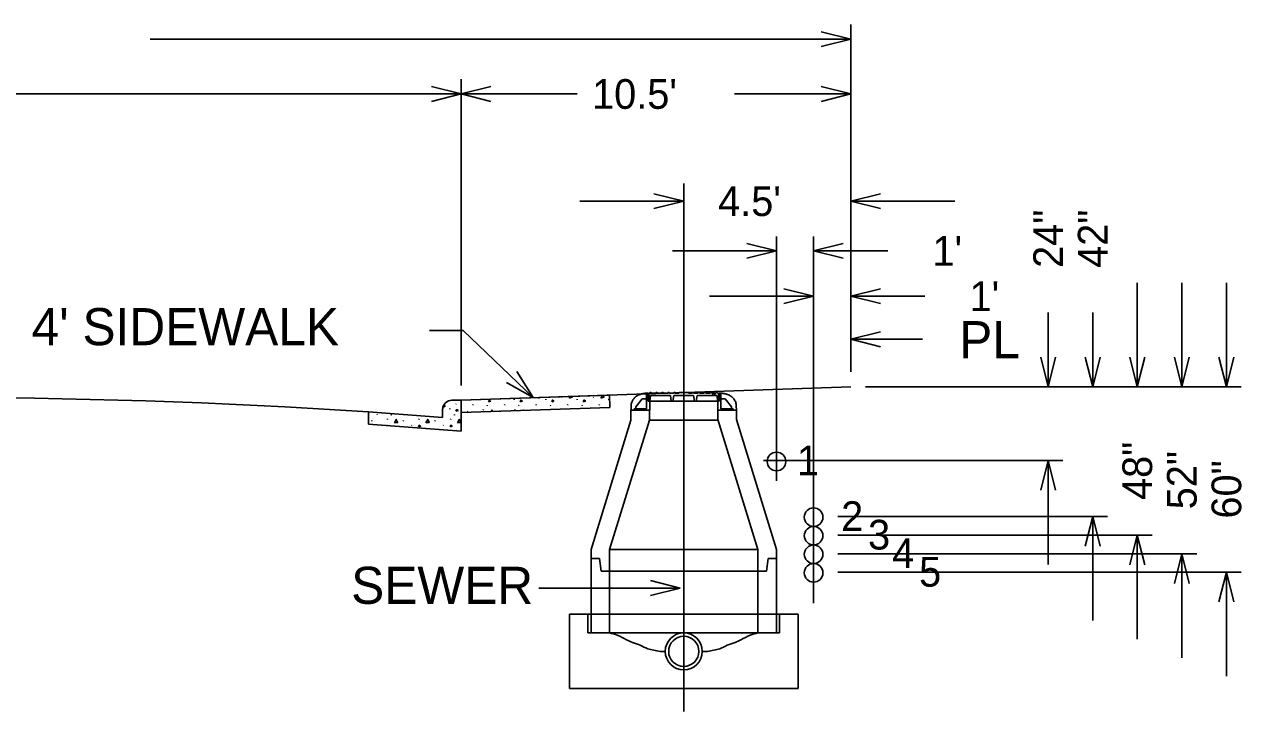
# Model space of a CAD drawing. Extents: x 524397 to 525117, y 3701341 to 3701821.
# Drawn here: x 524790.7 to 524856.3, y 3701669.5 to 3701706.5 of the extents above; entities that cross this region are included whole.
import ezdxf

# ---------------------------------------------------------------- set-up
doc = ezdxf.new("R2010")
doc.units = 0
doc.layers.add('Level 11', color=7, linetype='Continuous')

msp = doc.modelspace()

# ---------------------------------------------------------------- linework, layer by layer
at = {"layer": 'Level 11'}
for p, q in [((524835.239, 3701687.802), (524835.239, 3701706.53)), ((524797.484, 3701705.729), (524835.239, 3701705.729)), ((524833.638, 3701706.13), (524835.239, 3701705.729)), ((524835.239, 3701705.729), (524833.638, 3701705.329)), ((524812.642, 3701703.179), (524814.243, 3701702.779)), ((524814.243, 3701687.069), (524814.243, 3701703.579)), ((524814.243, 3701702.779), (524815.844, 3701703.179)), ((524833.638, 3701703.179), (524835.239, 3701702.779)), ((524835.239, 3701687.802), (524835.239, 3701703.579)), ((524787.897, 3701702.779), (524814.243, 3701702.779)), ((524814.243, 3701702.779), (524812.642, 3701702.379)), ((524820.499, 3701702.779), (524814.243, 3701702.779)), ((524815.844, 3701702.379), (524814.243, 3701702.779)), ((524828.983, 3701702.779), (524835.239, 3701702.779)), ((524835.239, 3701702.779), (524833.638, 3701702.379)), ((524835.239, 3701687.802), (524835.239, 3701700.542)), ((524826.239, 3701669.489), (524826.239, 3701697.958)), ((524824.638, 3701697.402), (524826.239, 3701697.002)), ((524835.239, 3701697.002), (524836.84, 3701697.402)), ((524820.635, 3701697.002), (524826.239, 3701697.002)), ((524826.239, 3701697.002), (524824.638, 3701696.601)), ((524840.842, 3701697.002), (524835.239, 3701697.002)), ((524836.84, 3701696.601), (524835.239, 3701697.002)), ((524829.638, 3701694.722), (524831.239, 3701694.321)), ((524831.239, 3701681.923), (524831.239, 3701695.099)), ((524833.239, 3701675.335), (524833.239, 3701695.099)), ((524833.239, 3701694.321), (524834.84, 3701694.722)), ((524825.635, 3701694.321), (524831.239, 3701694.321)), ((524831.239, 3701694.321), (524829.638, 3701693.921)), ((524837.241, 3701694.321), (524833.239, 3701694.321)), ((524834.84, 3701693.921), (524833.239, 3701694.321)), ((524850.681, 3701692.605), (524850.681, 3701687.001)), ((524853.083, 3701692.605), (524853.083, 3701687.001)), ((524855.484, 3701692.605), (524855.484, 3701687.001)), ((524827.635, 3701691.88), (524833.239, 3701691.88)), ((524831.638, 3701692.28), (524833.239, 3701691.88)), ((524833.239, 3701691.88), (524831.638, 3701691.479)), ((524835.239, 3701691.88), (524836.84, 3701692.28)), ((524839.241, 3701691.88), (524835.239, 3701691.88)), ((524836.84, 3701691.479), (524835.239, 3701691.88)), ((524845.878, 3701691.004), (524845.878, 3701687.001)), ((524848.28, 3701691.004), (524848.28, 3701687.001)), ((524814.352, 3701690.028), (524812.547, 3701690.028)), ((524818.13, 3701686.417), (524814.352, 3701690.028)), ((524835.239, 3701689.555), (524836.84, 3701689.955)), ((524835.239, 3701689.555), (524839.115, 3701689.555)), ((524836.84, 3701689.154), (524835.239, 3701689.555)), ((524845.878, 3701687.001), (524845.478, 3701688.602)), ((524846.279, 3701688.602), (524845.878, 3701687.001)), ((524848.28, 3701687.001), (524847.88, 3701688.602)), ((524848.68, 3701688.602), (524848.28, 3701687.001)), ((524850.681, 3701687.001), (524850.281, 3701688.602)), ((524851.081, 3701688.602), (524850.681, 3701687.001)), ((524853.083, 3701687.001), (524852.682, 3701688.602)), ((524853.483, 3701688.602), (524853.083, 3701687.001)), ((524855.484, 3701687.001), (524855.084, 3701688.602)), ((524855.884, 3701688.602), (524855.484, 3701687.001)), ((524818.13, 3701686.417), (524816.696, 3701687.234)), ((524817.249, 3701687.812), (524818.13, 3701686.417)), ((524835.239, 3701687.001), (524814.249, 3701686.269)), ((524824.24, 3701686.646), (524824.24, 3701686.646)), ((524824.24, 3701686.646), (524824.324, 3701686.646)), ((524824.24, 3701686.354), (524824.24, 3701686.646)), ((524824.323, 3701686.229), (524824.324, 3701686.646)), ((524824.365, 3701686.646), (524824.365, 3701686.229)), ((524824.407, 3701686.646), (524824.365, 3701686.646)), ((524824.365, 3701686.646), (524824.407, 3701686.646)), ((524824.365, 3701686.229), (524824.365, 3701686.646)), ((524824.407, 3701686.646), (524824.423, 3701686.687)), ((524824.407, 3701686.646), (524824.423, 3701686.687)), ((524824.423, 3701686.687), (524824.485, 3701686.687)), ((524824.423, 3701686.687), (524824.485, 3701686.687)), ((524824.5, 3701686.646), (524824.485, 3701686.687)), ((524824.485, 3701686.687), (524824.5, 3701686.646)), ((524824.731, 3701686.646), (524824.5, 3701686.646)), ((524824.5, 3701686.646), (524824.731, 3701686.646)), ((524824.731, 3701686.646), (524824.746, 3701686.687)), ((524824.731, 3701686.646), (524824.746, 3701686.687)), ((524824.746, 3701686.687), (524824.806, 3701686.687)), ((524824.746, 3701686.687), (524824.806, 3701686.687)), ((524824.821, 3701686.646), (524824.806, 3701686.687)), ((524824.806, 3701686.687), (524824.821, 3701686.646)), ((524825.047, 3701686.646), (524824.821, 3701686.646)), ((524824.821, 3701686.646), (524825.047, 3701686.646)), ((524825.047, 3701686.646), (524825.062, 3701686.687)), ((524825.047, 3701686.646), (524825.062, 3701686.687)), ((524825.062, 3701686.687), (524825.13, 3701686.687)), ((524825.062, 3701686.687), (524825.13, 3701686.687)), ((524825.145, 3701686.646), (524825.13, 3701686.687)), ((524825.13, 3701686.687), (524825.145, 3701686.646)), ((524825.375, 3701686.646), (524825.145, 3701686.646)), ((524825.145, 3701686.646), (524825.375, 3701686.646)), ((524825.375, 3701686.646), (524825.39, 3701686.687)), ((524825.375, 3701686.646), (524825.39, 3701686.687)), ((524825.39, 3701686.687), (524825.455, 3701686.687)), ((524825.39, 3701686.687), (524825.455, 3701686.687)), ((524825.47, 3701686.646), (524825.455, 3701686.687)), ((524825.455, 3701686.687), (524825.47, 3701686.646)), ((524825.697, 3701686.646), (524825.47, 3701686.646)), ((524825.47, 3701686.646), (524825.697, 3701686.646)), ((524825.697, 3701686.646), (524825.712, 3701686.687)), ((524825.697, 3701686.646), (524825.712, 3701686.687)), ((524825.712, 3701686.687), (524825.771, 3701686.687)), ((524825.712, 3701686.687), (524825.771, 3701686.687)), ((524825.786, 3701686.646), (524825.771, 3701686.687)), ((524825.771, 3701686.687), (524825.786, 3701686.646)), ((524825.972, 3701686.646), (524825.786, 3701686.646)), ((524825.786, 3701686.646), (524825.972, 3701686.646)), ((524825.972, 3701686.646), (524825.988, 3701686.687)), ((524825.972, 3701686.646), (524825.988, 3701686.687)), ((524825.988, 3701686.687), (524826.239, 3701686.687)), ((524825.988, 3701686.687), (524826.49, 3701686.687)), ((524826.49, 3701686.687), (524826.239, 3701686.687)), ((524826.505, 3701686.646), (524826.49, 3701686.687)), ((524826.49, 3701686.687), (524826.505, 3701686.646)), ((524826.692, 3701686.646), (524826.505, 3701686.646)), ((524826.505, 3701686.646), (524826.692, 3701686.646)), ((524826.692, 3701686.646), (524826.707, 3701686.687)), ((524826.692, 3701686.646), (524826.707, 3701686.687)), ((524826.765, 3701686.687), (524826.707, 3701686.687)), ((524826.707, 3701686.687), (524826.765, 3701686.687)), ((524826.781, 3701686.646), (524826.765, 3701686.687)), ((524826.765, 3701686.687), (524826.781, 3701686.646)), ((524827.008, 3701686.646), (524826.781, 3701686.646)), ((524826.781, 3701686.646), (524827.008, 3701686.646)), ((524827.008, 3701686.646), (524827.023, 3701686.687)), ((524827.008, 3701686.646), (524827.023, 3701686.687)), ((524827.088, 3701686.687), (524827.023, 3701686.687)), ((524827.023, 3701686.687), (524827.088, 3701686.687)), ((524827.103, 3701686.646), (524827.088, 3701686.687)), ((524827.088, 3701686.687), (524827.103, 3701686.646)), ((524827.332, 3701686.646), (524827.103, 3701686.646)), ((524827.103, 3701686.646), (524827.332, 3701686.646)), ((524827.332, 3701686.646), (524827.347, 3701686.687)), ((524827.332, 3701686.646), (524827.347, 3701686.687)), ((524827.415, 3701686.687), (524827.347, 3701686.687)), ((524827.347, 3701686.687), (524827.415, 3701686.687)), ((524827.43, 3701686.646), (524827.415, 3701686.687)), ((524827.415, 3701686.687), (524827.43, 3701686.646)), ((524827.657, 3701686.646), (524827.43, 3701686.646)), ((524827.43, 3701686.646), (524827.657, 3701686.646)), ((524827.657, 3701686.646), (524827.672, 3701686.687)), ((524827.657, 3701686.646), (524827.672, 3701686.687)), ((524827.731, 3701686.687), (524827.672, 3701686.687)), ((524827.672, 3701686.687), (524827.731, 3701686.687)), ((524827.746, 3701686.646), (524827.731, 3701686.687)), ((524827.731, 3701686.687), (524827.746, 3701686.646)), ((524827.978, 3701686.646), (524827.746, 3701686.646)), ((524827.746, 3701686.646), (524827.8, 3701686.646)), ((524827.8, 3701686.646), (524827.8, 3701686.521)), ((524827.8, 3701686.646), (524827.8, 3701686.521)), ((524827.925, 3701686.646), (524827.925, 3701686.521)), ((524827.925, 3701686.646), (524827.978, 3701686.646)), ((524827.925, 3701686.521), (524827.925, 3701686.646)), ((524827.978, 3701686.646), (524827.993, 3701686.687)), ((524827.978, 3701686.646), (524827.993, 3701686.687)), ((524828.055, 3701686.687), (524827.993, 3701686.687)), ((524827.993, 3701686.687), (524828.055, 3701686.687)), ((524828.07, 3701686.646), (524828.055, 3701686.687)), ((524828.055, 3701686.687), (524828.07, 3701686.646)), ((524828.112, 3701686.646), (524828.07, 3701686.646)), ((524828.07, 3701686.646), (524828.112, 3701686.646)), ((524828.112, 3701686.646), (524828.112, 3701686.229)), ((524828.112, 3701686.646), (524828.112, 3701686.229)), ((524828.154, 3701686.229), (524828.154, 3701686.646)), ((524828.238, 3701686.646), (524828.154, 3701686.646)), ((524828.238, 3701686.354), (524828.238, 3701686.646)), ((524836.039, 3701687.001), (524846.679, 3701687.001)), ((524836.039, 3701687.001), (524849.08, 3701687.001)), ((524836.039, 3701687.001), (524851.482, 3701687.001)), ((524836.039, 3701687.001), (524853.883, 3701687.001)), ((524836.039, 3701687.001), (524856.284, 3701687.001)), ((524814.249, 3701686.268), (524813.736, 3701686.268)), ((524813.736, 3701686.268), (524813.749, 3701686.268)), ((524813.955, 3701686.055), (524813.969, 3701686.087)), ((524814.243, 3701686.268), (524822.239, 3701686.548)), ((524814.243, 3701685.608), (524814.243, 3701686.268)), ((524814.249, 3701684.607), (524814.249, 3701686.268)), ((524814.876, 3701686.002), (524814.89, 3701686.034)), ((524815.399, 3701686.309), (524815.401, 3701686.293)), ((524815.64, 3701686.002), (524815.654, 3701685.981)), ((524815.654, 3701685.994), (524815.668, 3701685.973)), ((524816.577, 3701686.002), (524816.592, 3701686.034)), ((524817.099, 3701686.325), (524817.102, 3701686.293)), ((524817.341, 3701686.002), (524817.355, 3701685.981)), ((524817.355, 3701685.994), (524817.37, 3701685.973)), ((524818.279, 3701686.002), (524818.293, 3701686.034)), ((524818.8, 3701686.325), (524818.804, 3701686.293)), ((524819.043, 3701686.002), (524819.057, 3701685.981)), ((524819.057, 3701685.994), (524819.071, 3701685.973)), ((524819.657, 3701686.415), (524819.671, 3701686.446)), ((524819.98, 3701686.002), (524819.995, 3701686.034)), ((524820.502, 3701686.325), (524820.505, 3701686.293)), ((524820.744, 3701686.002), (524820.758, 3701685.981)), ((524820.758, 3701685.994), (524820.773, 3701685.973)), ((524821.359, 3701686.415), (524821.373, 3701686.446)), ((524821.682, 3701686.002), (524821.696, 3701686.034)), ((524822.203, 3701686.325), (524822.207, 3701686.293)), ((524822.239, 3701686.548), (524822.262, 3701685.888)), ((524823.657, 3701685.917), (524824.007, 3701686.355)), ((524824.007, 3701686.355), (524824.24, 3701686.354)), ((524824.24, 3701685.813), (524824.24, 3701686.354)), ((524824.407, 3701686.229), (524824.323, 3701686.229)), ((524824.365, 3701686.229), (524828.112, 3701686.229)), ((524824.407, 3701686.229), (524824.365, 3701686.229)), ((524824.407, 3701686.229), (524824.458, 3701686.521)), ((524824.458, 3701686.521), (524824.407, 3701686.229)), ((524824.407, 3701685.729), (524824.407, 3701686.229)), ((524825.521, 3701686.521), (524824.458, 3701686.521)), ((524825.521, 3701686.521), (524824.458, 3701686.521)), ((524825.572, 3701686.229), (524825.521, 3701686.521)), ((524825.572, 3701686.229), (524825.521, 3701686.521)), ((524825.656, 3701686.229), (524825.572, 3701686.229)), ((524825.656, 3701686.229), (524825.708, 3701686.521)), ((524825.708, 3701686.521), (524825.656, 3701686.229)), ((524826.77, 3701686.521), (524825.708, 3701686.521)), ((524826.77, 3701686.521), (524825.708, 3701686.521)), ((524826.822, 3701686.229), (524826.77, 3701686.521)), ((524826.822, 3701686.229), (524826.77, 3701686.521)), ((524826.905, 3701686.229), (524826.822, 3701686.229)), ((524826.905, 3701686.229), (524826.956, 3701686.521)), ((524826.956, 3701686.521), (524826.905, 3701686.229)), ((524828.019, 3701686.521), (524826.956, 3701686.521)), ((524827.8, 3701686.521), (524826.956, 3701686.521)), ((524828.019, 3701686.521), (524827.925, 3701686.521)), ((524828.071, 3701686.229), (524828.019, 3701686.521)), ((524828.071, 3701686.229), (524828.019, 3701686.521)), ((524828.071, 3701685.729), (524828.071, 3701686.229)), ((524828.071, 3701686.229), (524828.154, 3701686.229)), ((524828.112, 3701686.229), (524828.071, 3701686.229)), ((524828.47, 3701686.355), (524828.238, 3701686.354)), ((524828.238, 3701685.813), (524828.238, 3701686.354)), ((524828.82, 3701685.917), (524828.47, 3701686.355)), ((524813.249, 3701685.344), (524809.249, 3701685.646)), ((524809.249, 3701685.646), (524809.249, 3701684.984)), ((524809.714, 3701685.497), (524809.728, 3701685.529)), ((524810.268, 3701685.234), (524810.282, 3701685.266)), ((524810.478, 3701685.497), (524810.492, 3701685.476)), ((524810.492, 3701685.489), (524810.506, 3701685.468)), ((524811.969, 3701685.234), (524811.984, 3701685.266)), ((524813.249, 3701685.806), (524813.249, 3701685.344)), ((524813.638, 3701685.82), (524813.642, 3701685.788)), ((524813.671, 3701685.234), (524813.685, 3701685.266)), ((524813.881, 3701685.497), (524813.895, 3701685.476)), ((524813.895, 3701685.489), (524813.909, 3701685.468)), ((524822.262, 3701685.888), (524814.243, 3701685.608)), ((524814.588, 3701685.657), (524814.602, 3701685.689)), ((524815.43, 3701685.739), (524815.444, 3701685.771)), ((524816.3, 3701685.68), (524816.304, 3701685.689)), ((524817.132, 3701685.739), (524817.146, 3701685.771)), ((524818.846, 3701685.769), (524818.847, 3701685.771)), ((524823.397, 3701685.729), (524823.397, 3701685.196)), ((524824.407, 3701685.729), (524823.397, 3701685.729)), ((524823.397, 3701685.729), (524823.574, 3701685.729)), ((524823.574, 3701685.729), (524823.574, 3701685.813)), ((524823.574, 3701685.813), (524823.657, 3701685.813)), ((524823.657, 3701685.813), (524823.657, 3701685.917)), ((524823.657, 3701685.813), (524824.24, 3701685.813)), ((524824.396, 3701685.197), (524824.396, 3701685.729)), ((524824.396, 3701685.563), (524824.396, 3701685.237)), ((524829.081, 3701685.729), (524828.071, 3701685.729)), ((524828.082, 3701685.729), (524828.082, 3701685.23)), ((524829.081, 3701685.729), (524828.082, 3701685.729)), ((524828.082, 3701685.396), (524828.082, 3701685.57)), ((524828.82, 3701685.813), (524828.238, 3701685.813)), ((524828.82, 3701685.813), (524828.82, 3701685.917)), ((524828.904, 3701685.813), (524828.82, 3701685.813)), ((524828.904, 3701685.729), (524828.904, 3701685.813)), ((524829.081, 3701685.729), (524828.904, 3701685.729)), ((524829.081, 3701685.23), (524829.081, 3701685.729)), ((524809.249, 3701684.984), (524814.249, 3701684.607)), ((524809.426, 3701685.152), (524809.44, 3701685.184)), ((524811.128, 3701685.152), (524811.142, 3701685.184)), ((524811.572, 3701684.925), (524811.586, 3701684.904)), ((524812.829, 3701685.152), (524812.843, 3701685.184)), ((524813.273, 3701684.925), (524813.287, 3701684.904)), ((524823.397, 3701685.196), (524821.246, 3701678.229)), ((524824.396, 3701685.197), (524822.246, 3701678.23)), ((524824.396, 3701685.197), (524828.082, 3701685.197)), ((524828.082, 3701685.23), (524830.241, 3701678.234)), ((524829.081, 3701685.23), (524831.24, 3701678.234)), ((524830.539, 3701683.03), (524846.679, 3701683.03)), ((524845.478, 3701681.429), (524845.878, 3701683.03)), ((524845.878, 3701677.426), (524845.878, 3701683.03)), ((524845.878, 3701683.03), (524846.279, 3701681.429)), ((524834.539, 3701680.001), (524849.08, 3701680.001)), ((524847.88, 3701678.4), (524848.28, 3701680.001)), ((524848.28, 3701674.398), (524848.28, 3701680.001)), ((524848.28, 3701680.001), (524848.68, 3701678.4)), ((524834.539, 3701679.001), (524851.482, 3701679.001)), ((524850.281, 3701677.4), (524850.681, 3701679.001)), ((524850.681, 3701673.398), (524850.681, 3701679.001)), ((524850.681, 3701679.001), (524851.081, 3701677.4)), ((524821.246, 3701678.229), (524821.246, 3701677.068)), ((524830.241, 3701678.234), (524822.246, 3701678.23)), ((524822.246, 3701677.068), (524822.246, 3701678.23)), ((524830.241, 3701678.234), (524830.241, 3701677.068)), ((524830.241, 3701678.234), (524830.241, 3701677.734)), ((524831.24, 3701677.734), (524831.24, 3701678.234)), ((524831.24, 3701677.734), (524831.24, 3701678.234)), ((524821.246, 3701677.936), (524821.246, 3701677.734)), ((524821.246, 3701677.734), (524821.704, 3701677.734)), ((524821.246, 3701677.734), (524821.704, 3701677.734)), ((524821.246, 3701677.734), (524821.246, 3701676.347)), ((524821.704, 3701677.734), (524821.787, 3701677.068)), ((524821.704, 3701677.734), (524821.787, 3701677.068)), ((524822.246, 3701677.734), (524822.246, 3701677.936)), ((524822.246, 3701676.347), (524822.246, 3701677.734)), ((524830.241, 3701677.936), (524830.241, 3701677.734)), ((524830.241, 3701677.936), (524830.241, 3701677.734)), ((524830.241, 3701677.734), (524830.241, 3701673.737)), ((524830.241, 3701677.734), (524830.241, 3701673.737)), ((524830.699, 3701677.068), (524830.782, 3701677.734)), ((524830.699, 3701677.068), (524830.782, 3701677.734)), ((524830.782, 3701677.734), (524831.24, 3701677.734)), ((524830.782, 3701677.734), (524831.24, 3701677.734)), ((524830.782, 3701677.734), (524831.24, 3701677.734)), ((524831.24, 3701673.737), (524831.24, 3701677.936)), ((524831.24, 3701677.068), (524831.24, 3701677.734)), ((524834.539, 3701678.001), (524853.883, 3701678.001)), ((524852.682, 3701676.4), (524853.083, 3701678.001)), ((524853.083, 3701672.398), (524853.083, 3701678.001)), ((524853.083, 3701678.001), (524853.483, 3701676.4)), ((524821.246, 3701677.346), (524821.246, 3701673.737)), ((524821.787, 3701677.068), (524822.246, 3701677.068)), ((524821.787, 3701677.068), (524822.246, 3701677.068)), ((524822.246, 3701677.068), (524830.241, 3701677.068)), ((524822.246, 3701677.068), (524830.241, 3701677.068)), ((524830.241, 3701677.068), (524830.699, 3701677.068)), ((524830.241, 3701677.068), (524830.699, 3701677.068)), ((524834.539, 3701677.001), (524856.284, 3701677.001)), ((524855.084, 3701675.4), (524855.484, 3701677.001)), ((524855.484, 3701671.398), (524855.484, 3701677.001)), ((524855.484, 3701677.001), (524855.884, 3701675.4)), ((524826.054, 3701676.15), (524818.437, 3701676.15)), ((524822.246, 3701676.347), (524822.246, 3701675.163)), ((524824.453, 3701676.551), (524826.054, 3701676.15)), ((524826.054, 3701676.15), (524824.453, 3701675.75)), ((524822.246, 3701673.737), (524822.246, 3701675.163)), ((524821.246, 3701674.736), (524820.08, 3701674.736)), ((524820.08, 3701674.736), (524820.08, 3701670.739)), ((524821.08, 3701673.737), (524821.08, 3701674.736)), ((524821.246, 3701674.736), (524831.24, 3701674.736)), ((524831.24, 3701674.736), (524832.406, 3701674.736)), ((524831.407, 3701673.737), (524831.407, 3701674.736)), ((524832.406, 3701674.736), (524832.406, 3701670.739)), ((524821.246, 3701673.737), (524821.08, 3701673.737)), ((524821.246, 3701673.737), (524821.08, 3701673.737)), ((524821.246, 3701673.737), (524822.246, 3701673.737)), ((524822.246, 3701673.737), (524821.246, 3701673.737)), ((524822.246, 3701673.737), (524821.246, 3701673.737)), ((524822.246, 3701673.737), (524830.241, 3701673.737)), ((524830.241, 3701673.737), (524831.24, 3701673.737)), ((524830.241, 3701673.737), (524831.24, 3701673.737)), ((524831.24, 3701673.737), (524831.407, 3701673.737)), ((524832.406, 3701670.739), (524820.08, 3701670.739)), ((524820.08, 3701670.739), (524832.406, 3701670.739))]:
    msp.add_line(p, q, dxfattribs=at)
for points in [[(524813.313, 3701686.014), (524813.381, 3701685.944), (524813.277, 3701685.896)], [(524815.721, 3701686.187), (524815.764, 3701686.276), (524815.835, 3701686.223), (524815.721, 3701686.187)], [(524817.423, 3701686.187), (524817.466, 3701686.276), (524817.537, 3701686.223), (524817.423, 3701686.187)], [(524818.388, 3701686.378), (524818.393, 3701686.413)], [(524818.471, 3701686.416), (524818.391, 3701686.379)], [(524819.124, 3701686.187), (524819.167, 3701686.276), (524819.238, 3701686.223), (524819.124, 3701686.187)], [(524820.089, 3701686.378), (524820.103, 3701686.473)], [(524820.218, 3701686.477), (524820.245, 3701686.449), (524820.093, 3701686.379)], [(524820.826, 3701686.187), (524820.869, 3701686.276), (524820.94, 3701686.223), (524820.826, 3701686.187)], [(524821.791, 3701686.378), (524821.812, 3701686.533)], [(524821.864, 3701686.534), (524821.946, 3701686.449), (524821.794, 3701686.379)], [(524813.962, 3701685.682), (524814.005, 3701685.771), (524814.076, 3701685.718), (524813.962, 3701685.682)], [(524814.243, 3701685.656), (524814.264, 3701685.609)], [(524815.865, 3701685.665), (524815.906, 3701685.743), (524815.94, 3701685.667)], [(524817.598, 3701685.725), (524817.608, 3701685.743), (524817.615, 3701685.726)], [(524810.278, 3701684.906), (524810.286, 3701684.921), (524810.309, 3701684.904)], [(524810.648, 3701685.056), (524810.744, 3701685.238), (524810.819, 3701685.071), (524810.652, 3701685.056)], [(524811.945, 3701684.833), (524811.987, 3701684.921), (524812.058, 3701684.868), (524811.945, 3701684.833)], [(524812.35, 3701685.056), (524812.445, 3701685.238), (524812.52, 3701685.071), (524812.353, 3701685.056)], [(524813.646, 3701684.833), (524813.689, 3701684.921), (524813.76, 3701684.868), (524813.646, 3701684.833)], [(524814.051, 3701685.056), (524814.147, 3701685.238), (524814.222, 3701685.071), (524814.055, 3701685.056)]]:
    msp.add_lwpolyline(points, dxfattribs=at)
for centre, radius in [((524831.239, 3701682.971), 0.5), ((524833.239, 3701679.971), 0.5), ((524833.239, 3701678.971), 0.5), ((524833.239, 3701677.971), 0.5), ((524833.239, 3701676.971), 0.5), ((524826.243, 3701672.737), 0.999), ((524826.243, 3701672.737), 0.814)]:
    msp.add_circle(centre, radius, dxfattribs=at)
for centre, radius, start, end in [((524785.243, 3701317.884), 368.545, 86.2653, 93.7347), ((524813.743, 3701685.774), 0.494, 89.23325, 176.29205)]:
    msp.add_arc(centre, radius, start, end, dxfattribs=at)
for points in [[(524824.24, 3701686.646), (524824.167, 3701686.645), (524824.088, 3701686.634), (524824.019, 3701686.622), (524823.96, 3701686.61), (524823.896, 3701686.582), (524823.838, 3701686.569), (524823.695, 3701686.489), (524823.591, 3701686.404), (524823.5, 3701686.285), (524823.424, 3701686.121), (524823.403, 3701685.889), (524823.397, 3701685.729)], [(524828.238, 3701686.646), (524828.31, 3701686.645), (524828.39, 3701686.634), (524828.458, 3701686.622), (524828.517, 3701686.61), (524828.581, 3701686.582), (524828.64, 3701686.569), (524828.783, 3701686.489), (524828.886, 3701686.404), (524828.977, 3701686.285), (524829.054, 3701686.121), (524829.074, 3701685.889), (524829.081, 3701685.729)], [(524822.246, 3701673.737), (524822.66, 3701673.612), (524823.163, 3701673.361), (524823.479, 3701673.214), (524823.898, 3701673.067), (524824.297, 3701672.879), (524824.633, 3701672.795), (524824.969, 3701672.732), (524825.244, 3701672.737)], [(524830.241, 3701673.737), (524829.827, 3701673.612), (524829.323, 3701673.361), (524829.008, 3701673.214), (524828.588, 3701673.067), (524828.189, 3701672.879), (524827.853, 3701672.795), (524827.517, 3701672.732), (524827.243, 3701672.737)]]:
    msp.add_spline(points, degree=3, dxfattribs=at)

# ---------------------------------------------------------------- texts
for s, height, p in [("10.5'", 1.601, (524821.299, 3701701.977)), ("4.5'", 1.601, (524828.092, 3701696.199)), ("1'", 1.601, (524839.643, 3701693.519)), ("1'", 1.601, (524841.643, 3701691.077)), ("4' SIDEWALK", 2, (524791.097, 3701689.237)), ('PL', 2, (524841.085, 3701688.536)), ('1', 1.601, (524832.342, 3701682.226)), ('2', 1.601, (524834.724, 3701679.226)), ('3', 1.601, (524836.174, 3701678.226)), ('4', 1.601, (524837.473, 3701677.226)), ('5', 1.601, (524838.923, 3701676.226)), ('SEWER', 2, (524808.318, 3701675.299))]:
    msp.add_text(s, height=height, dxfattribs=at).set_placement(p)
for s, p in [('24"', (524846.679, 3701693.403)), ('42"', (524849.08, 3701693.403)), ('48"', (524851.482, 3701680.894)), ('52"', (524853.883, 3701680.394)), ('60"', (524856.285, 3701679.894))]:
    msp.add_text(s, height=1.601, rotation=90, dxfattribs=at).set_placement(p)

doc.saveas('drawing.dxf')
